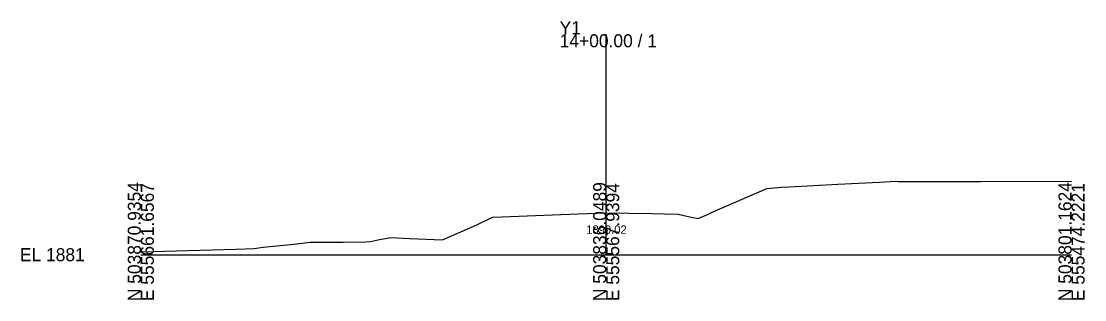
# Model space of a CAD drawing. Extents: x -26 to 1503, y -10 to 5015.
# Drawn here: x -25.7 to 202.8, y 3990.3 to 4050.2 of the extents above; entities that cross this region are included whole.
import ezdxf

# ---------------------------------------------------------------- set-up
doc = ezdxf.new("R2010")
doc.units = 0
for name, color, linetype in [('Default', 7, 'Continuous'), ('Exist Cross Section Cell', 7, 'Continuous'), ('Exist XS Center Line Elevation Label', 7, 'Continuous'), ('Exist XS Ground Line', 7, 'Continuous')]:
    doc.layers.add(name, color=color, linetype=linetype)

msp = doc.modelspace()

# ---------------------------------------------------------------- linework, layer by layer
at = {"layer": 'Exist Cross Section Cell'}
for p, q in [((100, 4000), (100, 4047.4)), ((0, 4000), (100, 4000)), ((100, 4000), (200, 4000))]:
    msp.add_line(p, q, dxfattribs=at)
at = {"layer": 'Exist XS Ground Line'}
for p, q in [((149.8, 4015.17), (158.7, 4015.62)), ((158.7, 4015.62), (162.23, 4015.79)), ((162.23, 4015.79), (162.74, 4015.77)), ((162.74, 4015.77), (180.47, 4015.71)), ((180.47, 4015.71), (200, 4015.8)), ((122.8, 4009.15), (134.56, 4014.23)), ((134.56, 4014.23), (137.68, 4014.5)), ((137.68, 4014.5), (139.29, 4014.58)), ((139.29, 4014.58), (149.8, 4015.17)), ((84.8, 4008.43), (93.94, 4008.79)), ((93.94, 4008.79), (100.04, 4009.02)), ((100.04, 4009.02), (109.73, 4008.88)), ((109.73, 4008.88), (115.48, 4008.74)), ((115.48, 4008.74), (118.26, 4008.04)), ((119.74, 4007.75), (121.76, 4008.63)), ((121.76, 4008.63), (122.8, 4009.15)), ((64.84, 4003.16), (72.21, 4006.4)), ((72.21, 4006.4), (75.55, 4008.07)), ((75.55, 4008.07), (77.59, 4008.12)), ((77.59, 4008.12), (84.8, 4008.43)), ((118.26, 4008.04), (119.74, 4007.75)), ((26.31, 4001.58), (32.85, 4002.26)), ((32.85, 4002.26), (36.42, 4002.7)), ((36.42, 4002.7), (43.48, 4002.71)), ((43.48, 4002.71), (48.38, 4002.79)), ((48.38, 4002.79), (49.38, 4002.85)), ((49.38, 4002.85), (51.28, 4003.24)), ((51.28, 4003.24), (53.75, 4003.67)), ((53.75, 4003.67), (57.73, 4003.47)), ((57.73, 4003.47), (64.84, 4003.16)), ((0, 4000.64), (20.43, 4001.2)), ((20.43, 4001.2), (24.34, 4001.32)), ((24.34, 4001.32), (26.31, 4001.58))]:
    msp.add_line(p, q, dxfattribs=at)

# ---------------------------------------------------------------- texts
at = {"layer": 'Default'}
msp.add_text('-', height=0.0001, dxfattribs=at).set_placement((0, 4000))
at = {"layer": 'Exist Cross Section Cell'}
for s, p in [('Y1', (90, 4047.4)), ('14+00.00 / 1', (90, 4044.6)), ('EL 1881', (-26, 3998.6))]:
    msp.add_text(s, height=2.8, dxfattribs=at).set_placement(p)
for s, p in [('N 503870.9354', (0, 3990)), ('N 503836.0489', (100, 3990)), ('N 503801.1624', (200, 3990)), ('E 555661.6567', (2.8, 3990)), ('E 555567.9394', (102.8, 3990)), ('E 555474.2221', (202.8, 3990))]:
    msp.add_text(s, height=2.8, rotation=90, dxfattribs=at).set_placement(p)
at = {"layer": 'Exist XS Center Line Elevation Label'}
msp.add_text('1890.02', height=1.8, dxfattribs=at).set_placement((95.71, 4004.49))

doc.saveas('drawing.dxf')
